(* Logix 5000 project; controller ControlLogix 1756-L63 rev 16.20; software revision 16.03 *)

TASK MainTask (continuous, watchdog 500 ms) : MainProgram

MODULES
   Local : 1756-L63 (ICP 0, rev 16.20)
      Local_ENBT : 1756-ENBT (ICP 3, Ethernet 105.102.0.224, rev 1.1)
         RemoteENBT_Slot6 : 1756-ENBT (Ethernet 105.102.0.210, rev 1.1, Output RPI 20 ms)
            MNETCR : vendor 1 type 0 code 15 (ICP 1, rev 1.1, Output RPI 5 ms)
END_MODULES

TYPE MNETCRBLOCKSTATS :   // This object is used to store the block transfer statistics for the MVI56-MNETCR module.
STRUCT
   Read : INT;   // Total number of read block transfers
   Write : INT;   // Total number of write block transfers
   Parse : INT;   // Total number of blocks parsed
   Event : INT;   // Total number of event blocks received
   Cmd : INT;   // Total number of command blocks received
   Err : INT;   // Total number of block transfer errors
END_STRUCT
END_TYPE

TYPE MNETCRCLIENTSTATS :   // This object is used to store the port statistics for an MVI56-MNETCR port.
STRUCT
   CmdReq : INT;   // Total number of command list requests sent
   CmdResp : INT;   // Total number of command list responses received
   CmdErr : INT;   // Total number of command list errors
   Requests : INT;   // Total number of requests for port
   Responses : INT;   // Total number of responses for port
   ErrSent : INT;   // Total number of errors sent
   ErrRec : INT;   // Total number of errors received
   CfgErrWord : INT;   // Configuration Error Word
   CurErr : INT;   // Current Error code
   LastErr : INT;   // Last recorded error code
END_STRUCT
END_TYPE

TYPE MNETCRCLOCKTYPE :   // Allows read/write of clock value between the module and processor
STRUCT
   Read : BOOL;   // Reads current time from the module
   Write : BOOL;   // Writes current time from the module
   Config : MNETCRDATETIME;   // Date and time configuration read or written between the module and processor
END_STRUCT
END_TYPE

TYPE MNETCRCMDCONTROL :   // MVI56E-MNETCR Command Control
STRUCT
   ClientIDreq : INT;   // Requested Client ID.
   CmdQty : INT;   // Command Quantaty for the Client.
   CmdIndex : INT[16];   // Command Index per client. (0 to 15)
END_STRUCT
END_TYPE

TYPE MNETCRCONTROL :   // Values used by program for data transfer operation between the module and the processor.
STRUCT
   BootTimer : TIMER;   // Timer used to clear both cold and warm boot requests
   WarmBoot : BOOL;   // Partial reset of the Module.
   ColdBoot : BOOL;   // Full reset of the Module.
   EventCmdTrigger : BOOL;   // Initiates Event Command.
   EventCmdPending : BOOL;   // Allows Event Command.
   ClientID : INT;   // Client ID to poll a server with the Event Command.
   EventCmd : MNETCREVENTCMD;   // Holds Event Command configuration
   CmdControl : MNETCRCMDCONTROL;   // Holds Command Control status
   CmdControlTrigger : BOOL;   // Initiates Command Control.
   CmdControlPending : BOOL;   // Allows CmdControlTriger.
   IPAddress : MNETCRIPADDRESS;   // IP address statistics including triggers
   WriteCmdBits : INT[30];   // Selects individual clients to to activate its commands.
END_STRUCT
END_TYPE

TYPE MNETCRDATA :   // Contains Read Data (data read from the module to the processor) and Write Data (data written from the processor to the module)
STRUCT
   ReadData : INT[600];   // Data read from module
   WriteData : INT[600];   // Data to write to module
END_STRUCT
END_TYPE

TYPE MNETCRDATETIME :   // Stores the date and time value
STRUCT
   Year : DINT;   // Displays module current year
   Month : DINT;   // Displays Module current month
   Day : DINT;   // Displays Module current day
   Hour : DINT;   // Displays Module current hour
   Minute : DINT;   // Displays Module current minute
   Seconds : DINT;   // Displays Module current second
END_STRUCT
END_TYPE

TYPE MNETCRETHERNET :   // Stores the MVI56E-MNETCR IP settings
STRUCT
   IP : INT[4];   // Module IP address
   Netmask : INT[4];   // Net mask used by the Module
   Gateway : INT[4];   // Gateway used by the module
END_STRUCT
END_TYPE

TYPE MNETCRETHERNETTYPE :   // Allows read/write Ethernet settings between the module and processor
STRUCT
   Read : BOOL;   // Enable Ethernet configuration transfer from module to processor
   Write : BOOL;   // Enable Ethernet configuration transfer from processor to module
   Config : MNETCRETHERNET;   // Module ethernet configurations ip, netmask and gateway
END_STRUCT
END_TYPE

TYPE MNETCREVENTCMD :   // Data structure to use for Event message generation.
STRUCT
   IP0 : INT;   // First digit of IP address
   IP1 : INT;   // Second digit of IP address
   IP2 : INT;   // Third digit of IP address
   IP3 : INT;   // Last digit of IP address
   ServPort : INT;   // TCP Service Port number (0-65535), 502 for MBAP, 2000 for MNET
   SlvAddrNode : INT;   // Modbus slave node address (0 to 247)
   DBAddress : INT;   // Module internal database to use with message
   Count : INT;   // Register or data point count
   Swap : INT;   // Swap code to use with functions 3 and 4
   MBFunction : INT;   // Modbus function code for message
   Address : INT;   // Address to interface with in device
END_STRUCT
END_TYPE

TYPE MNETCRIPADDRESS :   // This object holds IP address status with set IP & get IP triggers.
STRUCT
   IPgetTrigger : BOOL;   // Triggers get IP address.
   IPreceived : INT[4];   // Displays received IP address.
   IPsetTrigger : BOOL;   // Triggers set IP address
   IPrequested : INT[4];   // Displays requested IP address
END_STRUCT
END_TYPE

TYPE MNETCRMODULEDEF :   // This defines the whole module which includes all tags used in the program
STRUCT
   DATA : MNETCRDATA;   // Data read from module
   CONTROL : MNETCRCONTROL;   // MNETCR Module control
   STATUS : MNETCRSTATUS;   // Client ,Server Status and blocks status
   UTIL : MNETCRUTIL;   // Block statistics
END_STRUCT
END_TYPE

TYPE MNETCRSTATUS :   // This status data is returned on each read block and can be used to detect proper module operation.
STRUCT
   PassCnt : INT;   // Program cycle counter
   BlockStats : MNETCRBLOCKSTATS;   // Block Statistics
   CmdBits : INT[30];   // Client Command Status.
   ClientStatsTrigger : BOOL;   // Get Client Status
   ClientIDReq : INT;   // Client ID requested.
   ClientStatus : MNETCRCLIENTSTATS[30];   // Client Status requests
   ClientIDRec : INT;   // Client ID received.
   CmdErrorList : INT[16];   // Cmd Error List
   ClientStatsPending : BOOL;   // Allows Get Client Status
END_STRUCT
END_TYPE

TYPE MNETCRUTIL :   // Values used by program for data transfer operation between the module and the processor.
STRUCT
   LastRead : INT;   // Index of last read block
   LastWrite : INT;   // Index of last write block
   BlockIndex : INT;   // Computed block offset for data table
   ReadDataSizeGet : INT;   // Gets ReadData Array Length.
   WriteDataSizeGet : INT;   // Gets WriteData Array Length.
   ReadDataBlkCount : INT;   // Holds the value of the Block Counts of the Read Data Array.
   WriteDataBlkCount : INT;   // Holds the value of the Block Counts of the Write Data Array.
   RBTSremainder : INT;   // Holds remainder calculation value from the read array.
   WBTSremainder : INT;   // Holds remainder calculation value from the write array.
   IPgetPending : BOOL;   // Allows setting IP
   IPsetPending : BOOL;   // Allowes getting IP
END_STRUCT
END_TYPE

ADD_ON_INSTRUCTION AOI56MNETCR   (* revision 1.3 *)
// Add-On for MVI56-MNETCR and  MVI56E-MNETCR Modules
// Revision note:
// v1.3 - Logic now allowing no limitation on read & write data array string size allowing for flexible I/O and reformated  tags
VAR_IN_OUT
   Connection_Input : INT[42]; {required}   // Input parameters.
   Connection_Output : INT[42]; {required}   // Output parameters.
   MNETCR : MNETCRMODULEDEF; {required}
END_VAR
VAR
   MJFAULTS : DINT[12];
END_VAR

ROUTINE Logic   (* ladder *)
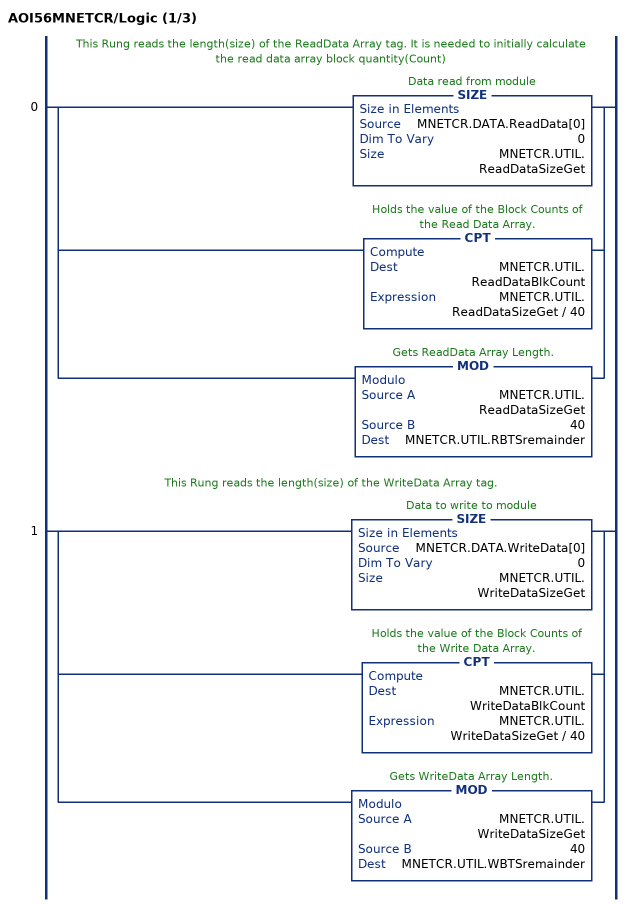
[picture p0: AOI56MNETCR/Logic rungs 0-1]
   // This Rung reads the length(size) of the ReadData Array tag. It is needed to initially calculate the read data array block quantity(Count)
   0: [SIZE(MNETCR.DATA.ReadData[0],0,MNETCR.UTIL.ReadDataSizeGet) ,CPT(MNETCR.UTIL.ReadDataBlkCount,MNETCR.UTIL.ReadDataSizeGet / 40) ,MOD(MNETCR.UTIL.ReadDataSizeGet,40,MNETCR.UTIL.RBTSremainder) ];
   // This Rung reads the length(size) of the WriteData Array tag.
   1: [SIZE(MNETCR.DATA.WriteData[0],0,MNETCR.UTIL.WriteDataSizeGet) ,CPT(MNETCR.UTIL.WriteDataBlkCount,MNETCR.UTIL.WriteDataSizeGet / 40) ,MOD(MNETCR.UTIL.WriteDataSizeGet,40,MNETCR.UTIL.WBTSremainder) ];
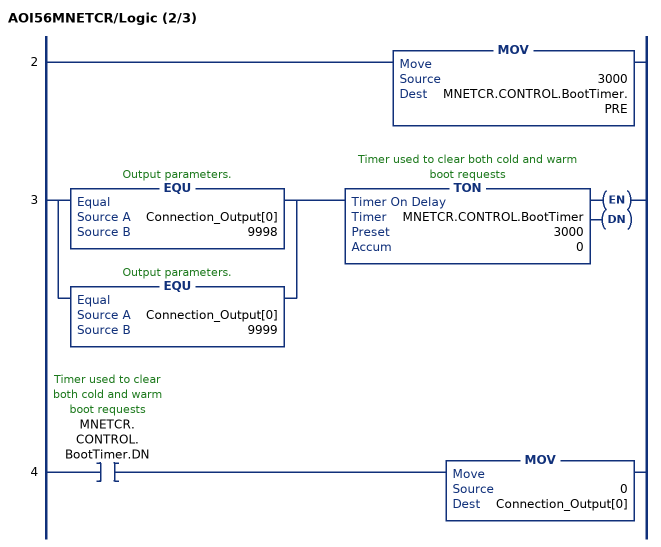
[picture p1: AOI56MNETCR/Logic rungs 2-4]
   2: MOV(3000,MNETCR.CONTROL.BootTimer.PRE);
   3: [EQU(Connection_Output[0],9998) ,EQU(Connection_Output[0],9999) ]TON(MNETCR.CONTROL.BootTimer,3000,0);
   4: XIC(MNETCR.CONTROL.BootTimer.DN)MOV(0,Connection_Output[0]);
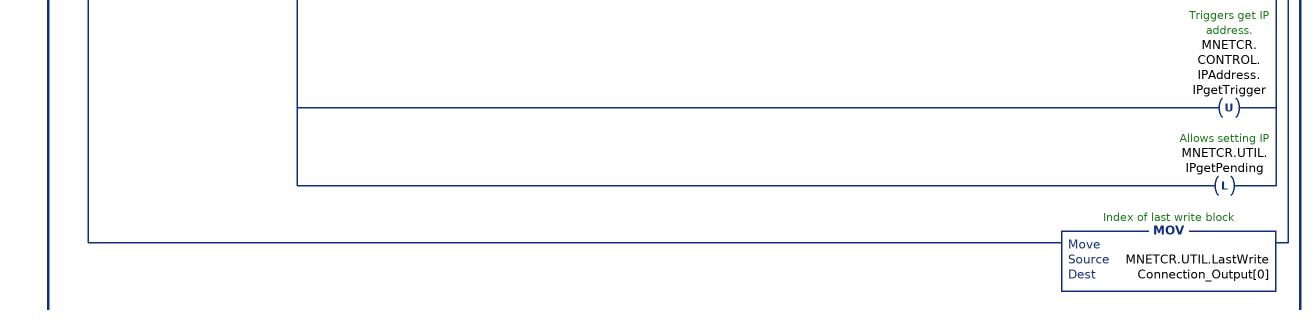
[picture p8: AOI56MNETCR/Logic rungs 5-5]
   // This rung is used to check for a new read block from the MVI56-MNETCR module in slot 1.  If new data is available, the LastRead and Data[41] will not be equal.  This will force the program to call the ReadData subroutine to process the new data received.  After the new data is placed in the Modbus Data Table, the program will send new data to the module using the WriteData subroutine.
   5: NEQ(Connection_Input[41],MNETCR.UTIL.LastRead)[MOV(Connection_Input[41],MNETCR.UTIL.LastRead) ,[EQU(-1,MNETCR.UTIL.LastRead) ,EQU(0,MNETCR.UTIL.LastRead) ] [MOV(Connection_Input[1],MNETCR.STATUS.PassCnt) ,COP(Connection_Input[2],MNETCR.STATUS.BlockStats.Read,6) ,COP(Connection_Input[8],MNETCR.STATUS.CmdBits[0],30) ] ,GEQ(MNETCR.UTIL.LastRead,1) [LEQ(MNETCR.UTIL.LastRead,MNETCR.UTIL.ReadDataBlkCount) [CPT(MNETCR.UTIL.BlockIndex,(MNETCR.UTIL.LastRead - 1) * 40) ,COP(Connection_Input[1],MNETCR.DATA.ReadData[MNETCR.UTIL.BlockIndex],40) ] ,CMP(MNETCR.UTIL.LastRead - MNETCR.UTIL.ReadDataBlkCount = 1) GRT(MNETCR.UTIL.RBTSremainder,0) [CPT(MNETCR.UTIL.BlockIndex,(MNETCR.UTIL.LastRead - 1) * 40) ,COP(Connection_Input[1],MNETCR.DATA.ReadData[MNETCR.UTIL.BlockIndex],MNETCR.UTIL.RBTSremainder) ] ] ,LIM(2000,MNETCR.UTIL.LastRead,2029) EQU(Connection_Input[1],1) OTU(MNETCR.CONTROL.EventCmdPending) ,LIM(3000,MNETCR.UTIL.LastRead,3029) [MOV(Connection_Input[1],MNETCR.STATUS.ClientIDRec) ,SUB(MNETCR.STATUS.ClientIDRec,3000,MNETCR.STATUS.ClientIDRec) ,COP(Connection_Input[2],MNETCR.STATUS.ClientStatus[MNETCR.STATUS.ClientIDRec],10) ,COP(Connection_Input[12],MNETCR.STATUS.CmdErrorList[0],16) ,OTU(MNETCR.STATUS.ClientStatsPending) ] ,LIM(5001,MNETCR.UTIL.LastRead,5016) LIM(1,Connection_Input[1],16) OTU(MNETCR.CONTROL.CmdControlPending) ,EQU(MNETCR.UTIL.LastRead,9990) [COP(Connection_Input[1],MNETCR.CONTROL.IPAddress.IPrequested[0],4) ,OTU(MNETCR.UTIL.IPsetPending) ] ,EQU(MNETCR.UTIL.LastRead,9991) [COP(Connection_Input[1],MNETCR.CONTROL.IPAddress.IPreceived[0],4) ,OTU(MNETCR.UTIL.IPgetPending) ] ,MOV(Connection_Input[0],MNETCR.UTIL.LastWrite) ,XIC(MNETCR.CONTROL.WarmBoot) [MOV(9998,MNETCR.UTIL.LastWrite) ,OTU(MNETCR.CONTROL.WarmBoot) ] ,XIC(MNETCR.CONTROL.ColdBoot) [MOV(9999,MNETCR.UTIL.LastWrite) ,OTU(MNETCR.CONTROL.ColdBoot) ] ,GEQ(MNETCR.UTIL.LastWrite,1) [LEQ(MNETCR.UTIL.LastWrite,MNETCR.UTIL.WriteDataBlkCount) [CPT(MNETCR.UTIL.BlockIndex,(MNETCR.UTIL.LastWrite - 1) * 40) ,COP(MNETCR.DATA.WriteData[MNETCR.UTIL.BlockIndex],Connection_Output[1],40) ] ,CMP(MNETCR.UTIL.LastWrite - MNETCR.UTIL.WriteDataBlkCount = 1) GRT(MNETCR.UTIL.WBTSremainder,0) [CPT(MNETCR.UTIL.BlockIndex,(MNETCR.UTIL.LastWrite - 1) * 40) ,COP(MNETCR.DATA.WriteData[MNETCR.UTIL.BlockIndex],Connection_Output[1],MNETCR.UTIL.WBTSremainder) ] ] ,[EQU(-1,MNETCR.UTIL.LastWrite) ,EQU(0,MNETCR.UTIL.LastWrite) ] COP(MNETCR.CONTROL.WriteCmdBits[0],Connection_Output[1],30) ,LIM(1000,MNETCR.UTIL.LastWrite,1124) [CPT(MNETCR.UTIL.BlockIndex,(MNETCR.UTIL.LastWrite - 1000) * 40) ,COP(MNETCR.DATA.ReadData[MNETCR.UTIL.BlockIndex],Connection_Output[1],40) ] ,XIC(MNETCR.CONTROL.EventCmdTrigger) XIO(MNETCR.CONTROL.EventCmdPending) [COP(MNETCR.CONTROL.EventCmd.IP0,Connection_Output[1],11) ,LIM(0,MNETCR.CONTROL.ClientID,29) ADD(2000,MNETCR.CONTROL.ClientID,MNETCR.UTIL.LastWrite) ,OTU(MNETCR.CONTROL.EventCmdTrigger) ,OTL(MNETCR.CONTROL.EventCmdPending) ] ,XIC(MNETCR.STATUS.ClientStatsTrigger) XIO(MNETCR.STATUS.ClientStatsPending) [LIM(0,MNETCR.STATUS.ClientIDreq,29) ADD(3000,MNETCR.STATUS.ClientIDreq,MNETCR.UTIL.LastWrite) ,OTU(MNETCR.STATUS.ClientStatsTrigger) ,OTL(MNETCR.STATUS.ClientStatsPending) ] ,XIC(MNETCR.CONTROL.CmdControlTrigger) XIO(MNETCR.CONTROL.CmdControlPending) [LIM(0,MNETCR.CONTROL.CmdControl.ClientIDreq,29) MOV(MNETCR.CONTROL.CmdControl.ClientIDreq,Connection_Output[1]) ,COP(MNETCR.CONTROL.CmdControl.CmdIndex[0],Connection_Output[2],16) ,LIM(1,MNETCR.CONTROL.CmdControl.CmdQty,16) ADD(5000,MNETCR.CONTROL.CmdControl.CmdQty,MNETCR.UTIL.LastWrite) ,OTU(MNETCR.CONTROL.CmdControlTrigger) ,OTL(MNETCR.CONTROL.CmdControlPending) ] ,XIC(MNETCR.CONTROL.IPAddress.IPsetTrigger) XIO(MNETCR.UTIL.IPsetPending) [COP(MNETCR.CONTROL.IPAddress.IPrequested[0],Connection_Output[1],4) ,MOV(9990,MNETCR.UTIL.LastWrite) ,OTU(MNETCR.CONTROL.IPAddress.IPsetTrigger) ,OTL(MNETCR.UTIL.IPsetPending) ] ,XIC(MNETCR.CONTROL.IPAddress.IPgetTrigger) XIO(MNETCR.UTIL.IPgetPending) [MOV(9991,MNETCR.UTIL.LastWrite) ,OTU(MNETCR.CONTROL.IPAddress.IPgetTrigger) ,OTL(MNETCR.UTIL.IPgetPending) ] ,MOV(MNETCR.UTIL.LastWrite,Connection_Output[0]) ];
END_ROUTINE

ROUTINE Prescan   (* ladder *)
// Prescan
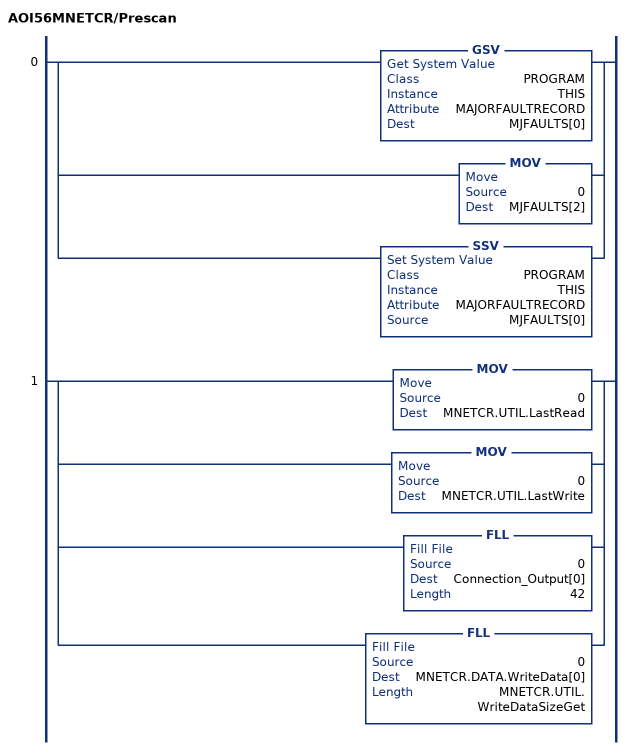
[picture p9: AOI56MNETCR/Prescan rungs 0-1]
   0: [GSV(PROGRAM,THIS,MAJORFAULTRECORD,MJFAULTS[0]) ,MOV(0,MJFAULTS[2]) ,SSV(PROGRAM,THIS,MAJORFAULTRECORD,MJFAULTS[0]) ];
   1: [MOV(0,MNETCR.UTIL.LastRead) ,MOV(0,MNETCR.UTIL.LastWrite) ,FLL(0,Connection_Output[0],42) ,FLL(0,MNETCR.DATA.WriteData[0],MNETCR.UTIL.WriteDataSizeGet) ];
END_ROUTINE
END_ADD_ON_INSTRUCTION

VAR_GLOBAL   (* controller tags *)
   AOI56MNETCR : AOI56MNETCR;
   MNETCR : MNETCRMODULEDEF;
        .BLK2000CLIENTID   // Client's Index ID.
        .BLK3000CLIENTID   // Holds Block 3000 Client ID
        .BLK5000CLIENTID   // Holds Block 5000 Client ID
        .BLK_1CLIENTID   // Holds Client ID for Command Bits Control.
        .BP.LASTREAD   // Index of last read block
        .BP.LASTWRITE   // Holds the value to be written on the last scan.
        .CMDCNTRL   // Initiates Command Control
        .COLDBOOT   // Re-initializes all the module's parameters
        .EVENTCMD   // Initiates an Event.
        .GETCLNTSTAT   // Initiates retreaval of Client Status.
        .GETIPADDRESS   // Initiates the retreaval of IP Address from the module.
        .HALTCLNTSTAT   // Halts Client Status Retreaval until the Module is ready for the next Status Retreaval.
        .HALTCMDBITCNTRL   // Halts Command Control Bits execution until the Module is ready for the next Command.
        .HALTCMDCNTRL   // Halts Command Control until the Module is ready for the next Command.
        .HALTEVENTCMD   // Halts Event Initiation until the Module is ready for the next Event.
        .HALTGETIPADDR   // Halts the IP Retreaval until the module is ready.
        .HALTSETIPADDRESS   // Halts the IP Adress Setting until the Module is ready for it.
        .INSTAT.CMDERRORLIST[0]   // Reads Command related errors
        .READIPADDRESS.IP[0]   // Reads Module's set IP Address
        .SETIPADDRESS   // Initiates the setting of the IP Address for the module.
        .WARMBOOT   // Re-loads MNET.CFG file
        .WRITEIPADDRESSACK.IP[0]   // Ack. from the module that it has received the new IP Address
END_VAR

PROGRAM MainProgram   (* main routine MainRoutine *)

ROUTINE MainRoutine   (* ladder *)
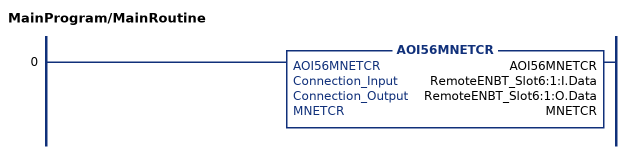
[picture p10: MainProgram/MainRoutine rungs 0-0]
   0: AOI56MNETCR(AOI56MNETCR,RemoteENBT_Slot6:1:I.Data,RemoteENBT_Slot6:1:O.Data,MNETCR);
END_ROUTINE
END_PROGRAM
